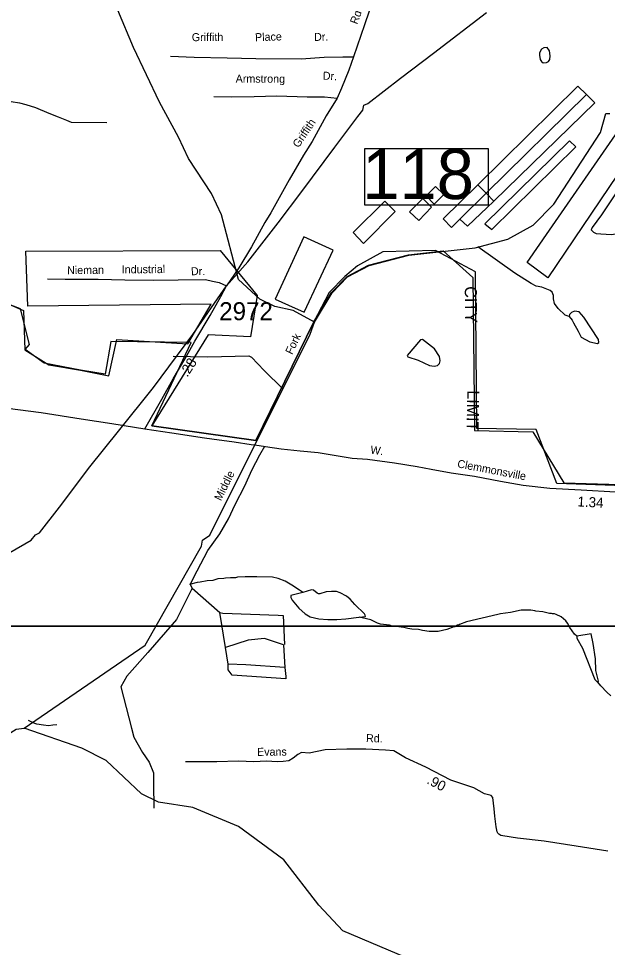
# Model space of a CAD drawing. Extents: x 1551653 to 1702041, y 811336 to 920032.
# Drawn here: x 1609613 to 1614440, y 828674 to 836287 of the extents above; entities that cross this region are included whole.
import ezdxf

# ---------------------------------------------------------------- set-up
doc = ezdxf.new("R2010")
doc.units = 0
for name, color, linetype in [('Old_Level_10', 7, 'Continuous'), ('Old_Level_11', 7, 'Continuous'), ('Old_Level_17', 7, 'Continuous'), ('Old_Level_19', 7, 'Continuous'), ('Old_Level_21', 7, 'Continuous'), ('Old_Level_31', 7, 'Continuous'), ('Old_Level_32', 7, 'Continuous'), ('Old_Level_35', 7, 'Continuous'), ('Old_Level_48', 7, 'Continuous'), ('Old_Level_49', 7, 'Continuous'), ('Old_Level_50', 7, 'Continuous'), ('Old_Level_56', 7, 'Continuous'), ('Old_Level_59', 7, 'Continuous'), ('Old_Level_62', 7, 'Continuous'), ('Old_Level_63', 7, 'Continuous'), ('Old_Level_8', 7, 'Continuous')]:
    doc.layers.add(name, color=color, linetype=linetype)

msp = doc.modelspace()

# ---------------------------------------------------------------- linework, layer by layer
at = {"layer": 'Old_Level_31'}
msp.add_line((1611549.499, 832792.732), (1611549.499, 832792.732), dxfattribs=at)
msp.add_lwpolyline([(1612452.168, 835220.871), (1613463.177, 835220.871), (1613463.177, 834756.638), (1612452.168, 834756.638), (1612452.168, 835220.871)], dxfattribs=at)
at = {"layer": 'Old_Level_32'}
for points in [[(1610647.36, 832924.903), (1610786.743, 833167.438), (1610879.167, 833333.903), (1610974.672, 833494.203), (1611057.854, 833642.172), (1611184.167, 833851.794), (1611270.43, 834009.012), (1611316.642, 834095.326)], [(1606884.744, 833997.022), (1607074.729, 833893.402), (1607257.272, 833797.047), (1607471.625, 833690.443), (1607656.316, 833591.44), (1607806.791, 833512.346), (1607909.967, 833459.026), (1608019.183, 833407.582), (1608061.515, 833389.653), (1608216.02, 833335.151), (1608283.761, 833311.524), (1608467.073, 833263.998), (1608608.027, 833239.992), (1608838.951, 833200.981), (1609063.878, 833164.97), (1609171.843, 833149.966), (1609264.812, 833137.963), (1609522.728, 833092.95), (1609798.638, 833056.94), (1610125.531, 833005.926), (1610377.448, 832966.915), (1610563.388, 832936.907), (1610647.36, 832924.903)], [(1610647.36, 832924.903), (1610869.605, 832892.473), (1611135.947, 832849.488), (1611196.088, 832842.611), (1611379.95, 832816.82), (1611520.854, 832796.188), (1611549.499, 832792.732)], [(1611549.499, 832792.732), (1611635.982, 832780.713), (1611764.857, 832760.08), (1611920.367, 832743.747), (1612067.616, 832730.523), (1612215.92, 832705.92), (1612346.513, 832685.288), (1612474.518, 832675.445), (1612695.807, 832644.539), (1612881.135, 832616.367), (1612994.76, 832594.851), (1613160.242, 832564.881), (1613349.566, 832536.426), (1613562.853, 832495.678), (1613748.295, 832463.299), (1613967.714, 832438.637), (1614225.141, 832423.411), (1614504.573, 832407.735)], [(1614444.252, 829464.116), (1614183.111, 829503.433), (1613920.008, 829544.788), (1613702.597, 829569.611), (1613582.925, 829589.047), (1613565.776, 829591.996), (1613549.162, 829601.54), (1613541.34, 829610.503), (1613537.361, 829621.589), (1613528.014, 829663.804), (1613517.151, 829749.87), (1613510.15, 829810.167), (1613500.017, 829902.479), (1613486.953, 829919.352), (1613431.148, 829932.048), (1613345.744, 829983.406), (1613155.367, 830046.172), (1612951.02, 830152.773), (1612784.272, 830228.796), (1612689.705, 830284.273), (1612620.007, 830291.091), (1612459.239, 830300.088), (1612302.581, 830300.088), (1612126.342, 830293.556), (1611995.622, 830266.808), (1611931.885, 830271.703), (1611901.514, 830254.108), (1611865.297, 830224.626), (1611829.037, 830202.95), (1611783.106, 830197.677), (1611733.05, 830196.29), (1611645.304, 830201.273), (1611540.801, 830194.848)]]:
    msp.add_lwpolyline(points, dxfattribs=at)
at = {"layer": 'Old_Level_35'}
for p, q in [((1611018.463, 831647.417), (1611037.005, 831619.886)), ((1611310.268, 831130.942), (1611263.344, 831418.231)), ((1611782.267, 831393.37), (1611793.308, 831155.804)), ((1611332.35, 830995.585), (1611310.268, 831130.942)), ((1611785.028, 831153.041), (1611796.069, 830967.96)), ((1611804.35, 830876.802), (1611362.712, 830904.425)), ((1610720.298, 830015.999), (1610720.721, 829815.94))]:
    msp.add_line(p, q, dxfattribs=at)
for points in [[(1612601.925, 836696.651), (1612575.164, 836609.622), (1612524.985, 836462.343), (1612448.044, 836234.729), (1612357.724, 835973.642)], [(1610859.773, 835977.618), (1611052.279, 835970.237), (1611323.912, 835964.729), (1611558.214, 835960.253), (1611929.534, 835956.906), (1612116.867, 835970.295), (1612270.747, 835973.642), (1612357.724, 835973.642)], [(1612357.724, 835973.642), (1612320.926, 835863.182), (1612260.712, 835715.902)], [(1612260.712, 835715.902), (1612223.914, 835635.568), (1612133.593, 835488.288), (1612020.055, 835278.719)], [(1608342.029, 835601.85), (1608664.138, 835601.85), (1609346.818, 835606.661), (1609491.046, 835606.661), (1609553.545, 835606.661), (1609620.851, 835597.04), (1609673.735, 835582.608), (1609750.656, 835558.555), (1609861.231, 835510.45), (1609938.153, 835481.587), (1610005.46, 835452.723), (1610043.92, 835438.292), (1610337.184, 835433.481)], [(1611213.656, 835648.957), (1611360.845, 835645.609), (1611544.833, 835648.957), (1611728.821, 835652.304), (1611979.713, 835645.609), (1612120.212, 835645.609), (1612223.914, 835635.568)], [(1612020.055, 835278.719), (1611949.587, 835167.612), (1611832.141, 834964.627), (1611680.53, 834695.405)], [(1611680.53, 834695.405), (1611631.416, 834616.349), (1611523.056, 834415.926), (1611418.309, 834243.295), (1611316.642, 834095.326)], [(1609850.177, 834153.897), (1609994.975, 834150.815), (1610266.086, 834150.815), (1610484.824, 834144.649), (1610718.965, 834141.566), (1610922.299, 834144.649), (1611144.117, 834147.732), (1611202.652, 834135.402), (1611258.107, 834123.071), (1611316.642, 834095.326)], [(1611018.463, 831647.417), (1611077.346, 831759.806), (1611165.377, 831926.715), (1611263.858, 832063.248), (1611333.389, 832186.305), (1611388.795, 832303.447), (1611466.778, 832458.352), (1611526.39, 832585.616), (1611589.956, 832710.596), (1611630.547, 832781.444)], [(1611037.005, 831619.886), (1610907.273, 831362.983), (1610672.653, 831092.269), (1610501.519, 830896.139), (1610451.835, 830810.504)], [(1611037.005, 831619.886), (1611263.344, 831418.231), (1611288.186, 831412.706)], [(1611288.186, 831412.706), (1611740.864, 831396.131), (1611782.267, 831393.37)], [(1611785.028, 831153.041), (1611627.694, 831205.526), (1611495.204, 831191.715), (1611310.268, 831130.942)], [(1611796.069, 830967.96), (1611475.882, 830990.06), (1611332.35, 830995.585)], [(1611362.712, 830904.425), (1611332.35, 830948.624), (1611332.35, 830995.585)], [(1611796.069, 830967.96), (1611804.35, 830893.376), (1611804.35, 830876.802)], [(1610451.835, 830810.504), (1610538.123, 830471.793), (1610557.445, 830397.209), (1610629.21, 830272.901), (1610684.415, 830192.791), (1610720.298, 830104.395), (1610720.298, 830015.999)], [(1611540.801, 830194.848), (1611415.564, 830200.328), (1611239.593, 830196.496), (1611081.906, 830196.493), (1610981.838, 830195.722)]]:
    msp.add_lwpolyline(points, dxfattribs=at)
at = {"layer": 'Old_Level_48'}
msp.add_lwpolyline([(1609012.435, 834169.682), (1609653.257, 833894.147), (1609664.798, 833572.297), (1609859.979, 833448.328), (1610122.021, 833404.62), (1610352.036, 833357.998), (1610419.002, 833655.211), (1611001.318, 833620.245), (1611190.571, 833946.596), (1609688.196, 833929.113), (1609673.638, 834380.76), (1611266.272, 834386.588), (1611569.076, 834016.529), (1611512.887, 833679.129), (1611167.278, 833696.005), (1610706.857, 832948.008), (1611556.967, 832828.256), (1612033.896, 833800.672), (1612178.971, 834040.695), (1612305.897, 834172.702), (1612481.94, 834264.313), (1612807.972, 834349.618), (1613093.799, 834381.841), (1613336.788, 834163.759), (1613349.278, 832911.657), (1613827.858, 832899.052), (1614082.953, 832481.366), (1614819.846, 832459.011)], dxfattribs=at)
at = {"layer": 'Old_Level_49'}
msp.add_lwpolyline([(1614813.374, 832449.661), (1614025.886, 832475.773), (1613855.189, 832917.678), (1613369.206, 832927.722), (1613358.241, 834211.761), (1613031, 834384.825), (1612598.44, 834373.538), (1612391.564, 834260.671), (1612286.162, 834173.885), (1612159.237, 834041.877), (1612033.896, 833800.672), (1611556.967, 832828.256), (1610706.857, 832948.008), (1611026.798, 833631.831), (1610368.367, 833640.731), (1610323.878, 833371.512), (1610122.021, 833404.62), (1609822.191, 833463.352), (1609666.932, 833573.28), (1609701.821, 833615.157), (1609628.554, 833906.552), (1609158.284, 834085.511)], dxfattribs=at)
at = {"layer": 'Old_Level_50'}
msp.add_line((1611556.859, 832809.724), (1611556.859, 832809.724), dxfattribs=at)
at = {"layer": 'Old_Level_56'}
msp.add_lwpolyline([(1609542.044, 831910.669), (1609717.391, 832011.972), (1609752.093, 832055.492), (1609784.261, 832072.851), (1609949.395, 832282.217), (1610198.457, 832614.155), (1610432.672, 832904.568), (1610718.111, 833263.984), (1611042.7, 833698.645), (1611316.642, 834095.326), (1611491.6, 834293.476), (1611740.379, 834611.409), (1611934.332, 834870.221), (1612205.812, 835231.919), (1612393.639, 835484.852), (1612434.305, 835536.256), (1612442.957, 835578.106), (1612475.25, 835591.659), (1612744.163, 835797.322), (1613015.082, 836003.141), (1613448.066, 836336.149)], dxfattribs=at)
at = {"layer": 'Old_Level_59'}
for points in [[(1612037.664, 833798.417), (1611864.412, 833894.226), (1611714.907, 833926.33), (1611590.218, 833987.591), (1611416.664, 834149.107), (1611277.779, 834676.842), (1611195.758, 834852.47), (1611004.714, 835138.996), (1610923.718, 835314.623), (1610769.673, 835602.42), (1610555.976, 836048.402), (1610299.539, 836665.446), (1610232.377, 836757.086), (1610226.272, 836922.038), (1610207.955, 837080.881), (1610198.654, 837233.245), (1610212.7, 837643.297), (1610264.681, 837799.804)], [(1612037.664, 833798.417), (1612182.738, 834038.431), (1612309.665, 834170.433), (1612485.703, 834262.04), (1612811.735, 834347.342), (1613354.713, 834408.55), (1613622.716, 834478.626), (1613831.665, 834592.532), (1614001.755, 834766.366), (1614383.665, 835352.763), (1614427.751, 835509.474), (1614460.764, 835508.757)], [(1611121.696, 832011.542), (1611180.649, 832053.014), (1612002.703, 833700.658), (1612037.664, 833798.417)], [(1609659.675, 830472.113), (1610651.717, 831151.143), (1611112.674, 831962.484), (1611121.696, 832011.542)], [(1606665.69, 828095.817), (1606891.923, 828225.693), (1607162.653, 828310.198), (1607833.566, 828602.676), (1608128.785, 828653.62), (1608244.337, 828846.102), (1608341.046, 828973.461), (1608539.466, 829644.02), (1608748.154, 829893.644), (1609155.657, 830193.397), (1609592.725, 830463.604), (1609659.675, 830472.113)], [(1614418.729, 827857.802), (1614244.742, 827976.219), (1613920.657, 828081.258), (1613280.69, 828215.669), (1612876.737, 828552.108), (1612271.731, 828810.628), (1612074.676, 829021.422), (1611787.705, 829391.591), (1611415.741, 829665.028), (1611042.649, 829820.355), (1610759.677, 829865.467), (1610619.729, 829933.954), (1610330.708, 830205.7), (1610132.73, 830308.226), (1609659.675, 830472.113)]]:
    msp.add_lwpolyline(points, dxfattribs=at)
at = {"layer": 'Old_Level_62'}
for p, q in [((1614267.4, 835664.084), (1613445.757, 834854.538)), ((1613507.785, 834790.459), (1614336.4, 835596.827)), ((1614267.4, 835664.084), (1614336.4, 835596.827)), ((1613378.294, 834924.102), (1613445.757, 834854.538)), ((1613230.964, 834643.283), (1613445.757, 834854.538)), ((1613445.757, 834854.538), (1613507.785, 834790.459))]:
    msp.add_line(p, q, dxfattribs=at)
for points in [[(1613883.645, 835985.708), (1613887.541, 835950.439), (1613898.512, 835934.855), (1613913.89, 835924.551), (1613940.035, 835925.32), (1613957.772, 835934.701), (1613968.639, 835950.592), (1613969.972, 835981.504), (1613964.026, 836022.156), (1613944.648, 836049.069), (1613919.017, 836047.224), (1613900.152, 836034.613), (1613884.363, 836005.956), (1613883.645, 835985.708)], [(1613378.294, 834924.102), (1614198.4, 835731.289), (1614267.4, 835664.084)], [(1613966.281, 834551.932), (1614579.49, 835440.935), (1614735.534, 835324.158), (1613951.415, 834160.847), (1613781.939, 834286.902), (1613966.281, 834551.932)], [(1614855.387, 835286.48), (1614810.891, 835308.164), (1614391.149, 834678.809), (1614314.357, 834573.719), (1614305.13, 834554.137), (1614324.61, 834535.785), (1614348.703, 834526.403), (1614386.433, 834521.431), (1614474.093, 834517.433), (1614522.588, 834524.455), (1614563.7, 834554.239), (1614611.17, 834606.681), (1614658.947, 834687.882), (1614678.017, 834729.866)], [(1613491.381, 834557.315), (1614180.971, 835235.063), (1614128.58, 835285.608), (1613434.479, 834604.836), (1613491.381, 834557.315)], [(1613031.039, 834909.543), (1612953.324, 834833.418), (1613018.531, 834766.673), (1613098.501, 834846.079), (1613031.039, 834909.543)], [(1613230.964, 834643.283), (1613162.067, 834574.745), (1613093.58, 834644.821), (1613378.294, 834924.102)], [(1612700.7, 834706.439), (1612614.783, 834789.947), (1612354.777, 834533.272), (1612441.719, 834442.076), (1612700.7, 834706.439)], [(1612892.834, 834630.57), (1612997.308, 834740.529), (1612926.667, 834812.81), (1612817.785, 834702.953), (1612892.834, 834630.57)], [(1613507.785, 834790.459), (1613292.993, 834584.279), (1613230.964, 834643.283)], [(1611956.566, 833886.538), (1612191.043, 834388.813), (1611950.414, 834498.26), (1611716.142, 833986.091), (1611826.665, 833936.725)], [(1613998.064, 834017.516), (1613987.607, 834043.403), (1613969.357, 834058.526), (1613901.075, 834085.08), (1613855.451, 834094.768), (1613814.543, 834114.659), (1613680.746, 834199.602), (1613378.775, 834414.842)], [(1614126.94, 833845.938), (1614094.234, 833855.473), (1614034.666, 833909.658), (1614005.446, 833950.719), (1613999.09, 833988.552), (1613998.064, 834017.516)], [(1611826.665, 833936.725), (1611953.49, 833880.028), (1611956.566, 833886.538)], [(1614126.94, 833845.938), (1614151.443, 833814.616), (1614160.773, 833792.009), (1614201.271, 833724.547), (1614223.314, 833675.95), (1614294.98, 833636.529), (1614358.546, 833624.841), (1614368.286, 833630.531), (1614365.313, 833656.982), (1614246.998, 833840.606), (1614206.91, 833882.95), (1614170.923, 833889.768), (1614145.702, 833877.823), (1614128.067, 833861.932), (1614126.94, 833845.938)], [(1612888.59, 833487.216), (1612982.299, 833442.361), (1613020.131, 833438.26), (1613046.89, 833443.899), (1613062.577, 833458.56), (1613068.831, 833482.243), (1613063.192, 833516.435), (1613023.104, 833579.233), (1612923.141, 833655.307), (1612906.737, 833654.743), (1612798.572, 833526.073), (1612805.134, 833513.411), (1612888.59, 833487.216)], [(1610881.375, 833520.828), (1611164.655, 833513.446), (1611500.735, 833521.597), (1611523.393, 833512.985), (1611624.997, 833402.974), (1611777.965, 833250.774)], [(1611944.365, 831582.983), (1611932.575, 831592.108), (1611916.683, 831602.31), (1611853.322, 831643.166), (1611797.753, 831675.974), (1611742.081, 831698.735), (1611694.304, 831707.399), (1611566.454, 831711.192), (1611470.49, 831710.525), (1611406.411, 831707.399), (1611390.417, 831703.605), (1611350.432, 831704.169), (1611310.447, 831700.735), (1611294.35, 831698.94), (1611246.368, 831693.66), (1611206.178, 831682.177), (1611158.195, 831678.845), (1611102.114, 831667.67), (1611078.02, 831663.979), (1611015.069, 831649.164)], [(1611944.365, 831582.983), (1611845.633, 831557.301), (1611843.89, 831542.844), (1611856.5, 831521.006), (1611909.609, 831455.287), (1611962.922, 831408.843), (1612004.445, 831383.467), (1612074.163, 831367.422), (1612147.367, 831361.014), (1612222.826, 831362.552), (1612295.927, 831368.088), (1612401.631, 831381.212), (1612405.937, 831381.622)], [(1612405.937, 831381.622), (1612457.611, 831386.39), (1612455.047, 831397.821), (1612449.819, 831408.176), (1612368.72, 831484.661), (1612331.401, 831527.671), (1612300.336, 831552.943), (1612248.457, 831580.882), (1612220.365, 831590.057), (1612179.457, 831592.108), (1612133.628, 831587.802), (1612082.878, 831573.09), (1612070.882, 831570.987), (1612061.142, 831576.576), (1612031.717, 831603.437), (1612014.903, 831603.591), (1611944.365, 831582.983)], [(1614187.738, 831224.449), (1614170.411, 831240.956), (1614131.246, 831297.5), (1614113.714, 831331.743), (1614099.975, 831349.89), (1614060.503, 831382.442), (1614020.723, 831402.999), (1614004.831, 831407.253), (1613988.837, 831407.458), (1613980.942, 831411.559), (1613964.948, 831411.765), (1613909.072, 831424.58), (1613853.195, 831429.348), (1613845.301, 831433.449), (1613813.312, 831437.909), (1613733.342, 831436.986), (1613645.17, 831420.223), (1613563.149, 831409.406), (1613541.003, 831401.717), (1613284.381, 831341.278), (1613228.094, 831320.106), (1613219.994, 831314.211), (1613211.997, 831314.314), (1613187.904, 831302.626), (1613179.907, 831302.779), (1613123.62, 831279.558), (1613051.441, 831264.537), (1612979.468, 831263.564), (1612923.591, 831270.33), (1612891.706, 831278.788), (1612835.829, 831283.556), (1612803.944, 831288.016), (1612772.058, 831296.474), (1612708.184, 831305.342), (1612684.193, 831305.65), (1612652.308, 831314.109), (1612580.539, 831323.131), (1612555.113, 831330.461), (1612532.352, 831342.457), (1612499.544, 831357.733), (1612405.937, 831381.622)], [(1614362.339, 830848.641), (1614366.03, 830855.612), (1614345.423, 830942.605), (1614341.937, 831039.339), (1614322.559, 831166.01), (1614305.335, 831243.007), (1614187.738, 831224.449)], [(1614187.738, 831224.449), (1614188.455, 831209.122), (1614236.335, 831125.461), (1614335.58, 830871.35), (1614354.342, 830851.255), (1614362.339, 830848.641)], [(1614467.326, 830734.939), (1614433.8, 830767.388), (1614386.535, 830818.601), (1614362.339, 830848.641)], [(1609927.986, 830497.181), (1609894.049, 830496.771), (1609858.78, 830491.286), (1609818.795, 830495.849), (1609763.021, 830504.614), (1609747.027, 830508.818), (1609694.021, 830533.937)]]:
    msp.add_lwpolyline(points, dxfattribs=at)
at = {"layer": 'Old_Level_63'}
for points in [[(1569096.749, 874749.337), (1631612.821, 874749.337), (1631612.821, 831307.151), (1569096.749, 831307.151), (1569096.749, 874749.337)], [(1577049.889, 831307.151), (1641328.558, 831307.151), (1641328.558, 811336.298), (1577049.889, 811336.298), (1577049.889, 831307.151)]]:
    msp.add_lwpolyline(points, dxfattribs=at)

# ---------------------------------------------------------------- texts
at = {"layer": 'Old_Level_10'}
for s, rotation, p in [('Rd.', 69.2552194, (1612388.224, 836234.935)), ('Griffith', 0.3256639, (1611033.343, 836101.164)), ('Place', 1.8352639, (1611552.393, 836100.795)), ('Dr.', 1.1084861, (1612035.615, 836103.342)), ('Armstrong', 359.8530611, (1611392.614, 835761.582)), ('Dr.', 357.1991972, (1612105.374, 835786.429)), ('Griffith', 56.1905667, (1611908.407, 835222.469)), ('Nieman', 0.5894889, (1610011.211, 834191.573)), ('Industrial', 0.4757194, (1610459.081, 834197.871)), ('Dr.', 0.2856861, (1611026.353, 834183.399))]:
    msp.add_text(s, height=65.6167, rotation=rotation, dxfattribs=at).set_placement(p)
at = {"layer": 'Old_Level_11'}
for s, height, rotation, p in [('W.', 65.6167, 352.0494361, (1612493.734, 832722.502)), ('Clemmonsville', 65.61666, 349.1841167, (1613205.522, 832609.389)), ('Rd.', 65.6167, 358.6689611, (1612460.309, 830356.909)), ('Evans', 65.6167, 0.4686194, (1611568.006, 830244.134))]:
    msp.add_text(s, height=height, rotation=rotation, dxfattribs=at).set_placement(p)
at = {"layer": 'Old_Level_17'}
for s, rotation, p in [('.28', 57.1181583, (1610996.219, 833342.647)), ('1.34', 356.7891361, (1614192.33, 832289)), ('.90', 332.4504583, (1612953.203, 830021.198))]:
    msp.add_text(s, height=82.0208, rotation=rotation, dxfattribs=at).set_placement(p)
at = {"layer": 'Old_Level_19'}
for s, rotation, p in [('CITY', 270.8101472, (1613269.892, 834091.854)), ('LIMIT', 268.7430389, (1613291.882, 833240.91))]:
    msp.add_text(s, height=98.425, rotation=rotation, dxfattribs=at).set_placement(p)
at = {"layer": 'Old_Level_21'}
for s, rotation, p in [('Fork', 64.4628583, (1611854.992, 833528.438)), ('Middle', 63.4841639, (1611271.643, 832329.293))]:
    msp.add_text(s, height=65.6167, rotation=rotation, dxfattribs=at).set_placement(p)
at = {"layer": 'Old_Level_31'}
msp.add_text('118', height=410.1042, dxfattribs=at).set_placement((1612430.843, 834807.285))
at = {"layer": 'Old_Level_8'}
msp.add_text('2972', height=147.6375, dxfattribs=at).set_placement((1611258.053, 833814.647))

doc.saveas('drawing.dxf')
